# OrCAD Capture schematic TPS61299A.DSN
size A
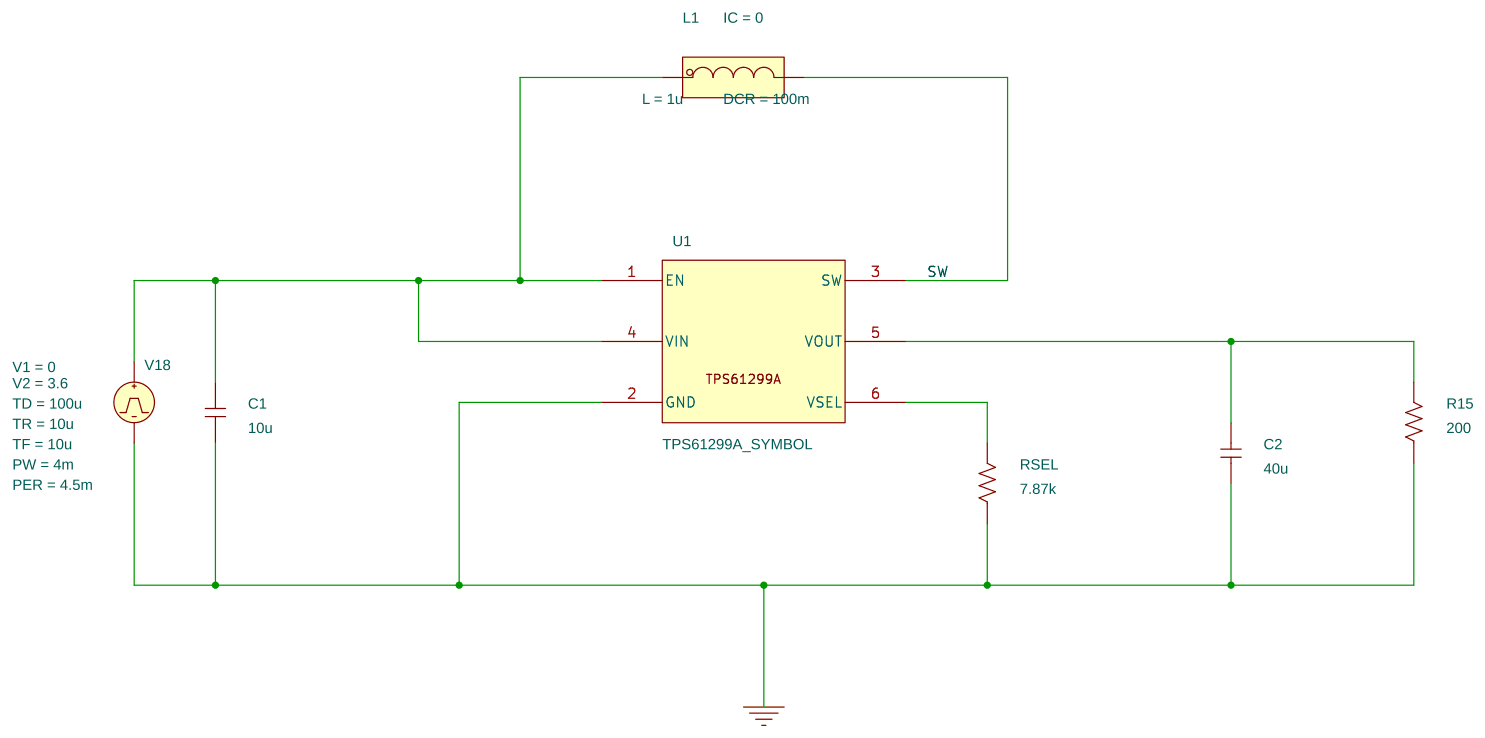
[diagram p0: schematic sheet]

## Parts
C1  10u  [RAD/CK05]
C2  40u  [RAD/CK05]
L1  LDCR
R15  200  [AX/RC05]
RSEL  7.87k  [AX/RC05]
U1  TPS61299A_SYMBOL
V18  VPULSE

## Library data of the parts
C1 C2 = C
L1 = LDCR: DCR: 100m; IC: 0; L: 1u; PSpiceTemplate: X^@REFDES %IN %OUT @MODEL PARAMS:  ?L|L=@L||L=1u|  ?DCR|DCR=@DCR||DCR=0.01| ?IC|IC=@IC||IC=0|
R15 RSEL = R
U1 = TPS61299A_SYMBOL_3
V18 = VPULSE: PER: 4.5m; PW: 4m; TD: 100u; TF: 10u; TR: 10u; V1: 0; V2: 3.6

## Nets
0: C1.2 C2.2 R15.1 RSEL.1 U1.2(GND) V18.2(-)
SW: L1.3(OUT) U1.3(SW)
N16776684: C1.1 L1.1(IN) U1.1(EN) U1.4(VIN) V18.1(+)
N16776776: C2.1 R15.2 U1.5(VOUT)
N16776860: RSEL.2 U1.6(VSEL)
